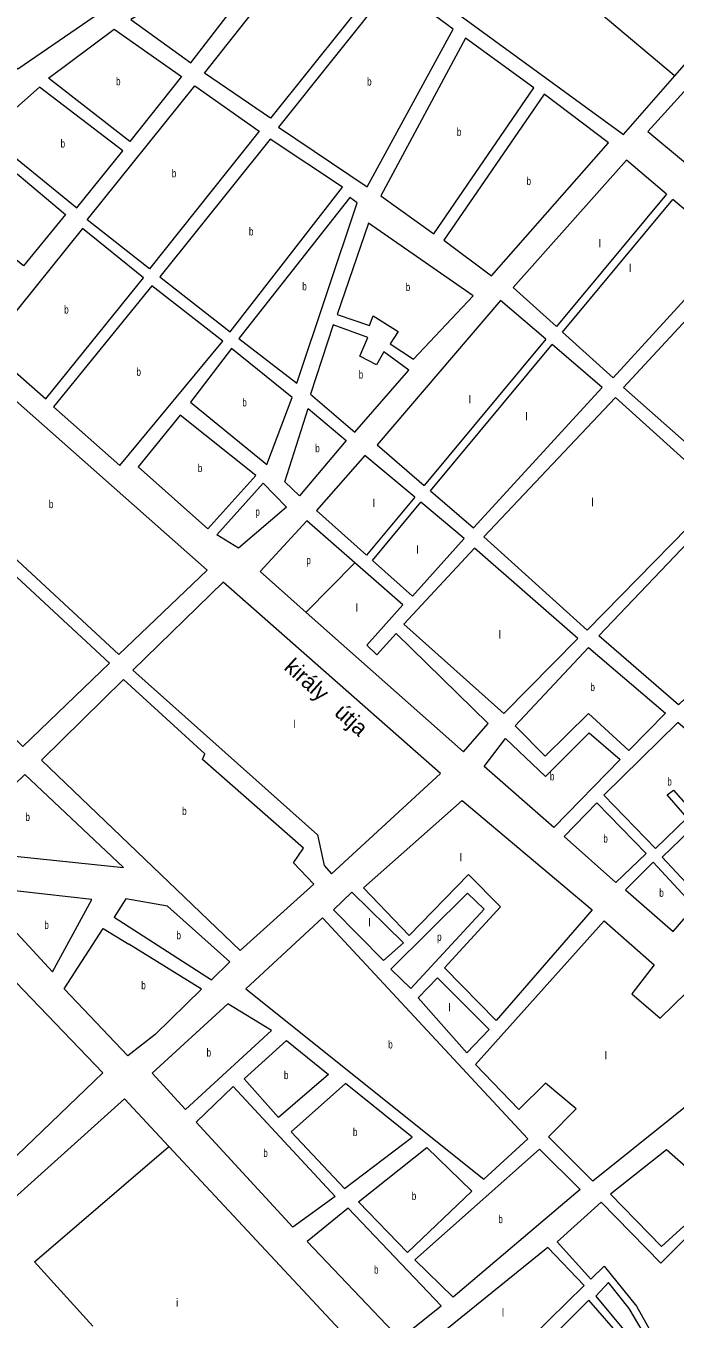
# Model space of a CAD drawing. Extents: x 639657 to 671642, y 222838 to 252123.
# Drawn here: x 655224 to 656035, y 240268 to 241884 of the extents above; entities that cross this region are included whole.
import ezdxf
from ezdxf.enums import TextEntityAlignment as Align

# ---------------------------------------------------------------- set-up
doc = ezdxf.new("R2010")
doc.units = 0
doc.header["$LTSCALE"] = 4
doc.layers.add('1', color=7, linetype='Continuous', lineweight=13)
doc.layers.add('21', color=7, linetype='Continuous', lineweight=13)
doc.layers.add('22', color=7, linetype='Continuous')
doc.layers.add('7', color=7, linetype='Continuous')

msp = doc.modelspace()

# ---------------------------------------------------------------- linework, layer by layer
at = {"layer": '1'}
for p, q in [((656024.414, 241674.151), (655886.753, 241508.509)), ((655894.364, 241501.644), (656032.279, 241667.507)), ((655832.72, 241557.25), (655886.753, 241508.509)), ((655873.616, 241492.701), (655721.745, 241309.96)), ((655729.45, 241303.309), (655881.391, 241486.042)), ((655662.94, 241360.72), (655721.745, 241309.96)), ((655709.772, 241295.553), (655649.539, 241223.076)), ((655657.126, 241216.327), (655717.574, 241289.026)), ((655586.77, 241278.92), (655649.539, 241223.076)), ((655516.47, 241202.55), (655574.023, 241151.538)), ((655443.06, 240680.6), (655352.25, 240736.81)), ((655385.49, 240624.22), (655443.06, 240680.6))]:
    msp.add_line(p, q, dxfattribs=at)
for points in [[(655304.45, 242218.19), (655077.93, 241931.43), (655213.74, 241830.45), (655396.658, 241956.518)], [(655630.564, 242060.254), (655599.16, 242019.65), (655970.83, 241748.67), (656034.683, 241821.83), (656138.378, 241940.64), (656234.597, 242050.884)], [(656024.414, 241674.151), (655974.33, 241716.45), (655832.72, 241557.25)], [(655894.364, 241501.644), (655957.88, 241444.35), (656105.39, 241605.76), (656032.279, 241667.507)], [(655873.616, 241492.701), (655816.92, 241541.26), (655662.94, 241360.72)], [(655729.45, 241303.309), (655783.18, 241256.93), (655944.01, 241432.41), (655881.391, 241486.042)], [(655709.772, 241295.553), (655647.46, 241347.69), (655586.77, 241278.92)], [(655657.126, 241216.327), (655707.05, 241171.91), (655771.47, 241243.93), (655717.574, 241289.026)], [(655634.809, 241213.583), (655575.06, 241265.93), (655516.47, 241202.55)], [(655574.023, 241151.538), (655770.56, 240977.34), (655801.43, 241012.53), (655686.49, 241124.97), (655662.53, 241098.44), (655650.05, 241110.69), (655694.77, 241161.05), (655634.809, 241213.583)], [(655385.49, 240624.22), (655351.31, 240597.6), (655271.56, 240681.31), (655320.37, 240756.43), (655352.25, 240736.81)], [(655105.621, 240170.224), (655025.29, 240254.65), (655346.94, 240543.81), (655402.598, 240484.128), (655650.81, 240217.97)]]:
    msp.add_lwpolyline(points, dxfattribs=at)
for points in [[(655566.4, 242015.61), (655355.12, 241892.37), (655429.78, 241838.18)], [(655447.09, 241825.43), (655587.48, 242002.89), (655669.17, 241943.38), (655529.3, 241769.14)], [(655682.13, 241936.5), (655539.61, 241757.95), (655650.46, 241683.09), (655757.88, 241880.17)], [(655353.76, 241739.72), (655252.01, 241818.95), (655334.26, 241880.37), (655418.11, 241820.88)], [(655773.03, 241869.01), (655667.22, 241671.95), (655733.76, 241624.67), (655858.51, 241806.84)], [(656058.32, 241702.64), (656107.08, 241658.98), (656223.11, 241792.71), (656104.21, 241865.88), (656000.9, 241752.14), (656050.72, 241711.18), (656107.16, 241774), (656115.82, 241767.08)], [(655174.13, 241748.97), (655287.28, 241656.93), (655344.72, 241728.36), (655240.82, 241807.57)], [(655515.46, 241752.91), (655378.26, 241580.84), (655300.31, 241642), (655434.87, 241809.2)], [(655871.48, 241798.89), (655746.19, 241616.71), (655805.71, 241572.07), (655952.1, 241738.3)], [(655528.99, 241742.81), (655391.25, 241570.74), (655478.93, 241502.14), (655619.28, 241682.83)], [(655220.72, 241584.36), (655161.06, 241632.7), (655212.73, 241699.31), (655273.38, 241648.75)], [(655628.53, 241670.01), (655489.76, 241493.63), (655562.28, 241437.81), (655637.73, 241663.1)], [(655294.5, 241631.2), (655174.83, 241482.93), (655248.5, 241418.51), (655370.83, 241569.49)], [(655651.93, 241637.96), (655612.6, 241523.69), (655653.04, 241510.05), (655657.77, 241521.92), (655689.12, 241502.29), (655679.04, 241487.16), (655708.24, 241468.06), (655782.81, 241547.15)], [(655970.88, 241432.64), (656104.16, 241314.44), (656226.68, 241442.85), (656219.64, 241449.78), (656246.84, 241474.73), (656118.41, 241591.89)], [(655381.13, 241559.37), (655258.26, 241408.38), (655341.15, 241334.91), (655469.9, 241490.24)], [(655651.02, 241494.99), (655607.88, 241510.75), (655579.6, 241423.98), (655634.84, 241376.61), (655702.45, 241454.03), (655671.07, 241476.88), (655662.07, 241460.68), (655641.01, 241471.79)], [(655480.73, 241481.19), (655429.7, 241414.12), (655524.99, 241336.45), (655556.52, 241420.02)], [(655450.34, 241204.15), (655155.63, 241464.49), (655052.75, 241364.74), (655339.97, 241098.95)], [(655796.18, 241245.75), (655960.78, 241420.19), (656092.99, 241300.37), (655925.14, 241129.13)], [(655511.13, 241322.36), (655416.4, 241397.89), (655364.28, 241333.49), (655450.96, 241255.75)], [(655576.53, 241406.22), (655624.18, 241366.31), (655565.65, 241297.02), (655547.22, 241314.6)], [(654947.24, 241256.9), (655220.01, 240984), (655328.24, 241088.11), (655043.72, 241351.76)], [(655462.56, 241248.47), (655520.36, 241312.76), (655549.64, 241282.91), (655489.42, 241231.91)], [(655939.71, 241122.26), (656103.26, 241293.47), (656209.99, 241198.16), (656039.37, 241036.03)], [(655784.48, 241231.68), (655696.06, 241136.88), (655821.21, 241025.06), (655913.4, 241118.82)], [(655470.36, 241189.27), (655357.34, 241079.21), (655588.14, 240873.69), (655596.54, 240835.06), (655605.77, 240824.93), (655741.76, 240950.22)], [(655927.12, 241025.28), (655872.76, 240972.04), (655835.16, 241009.89), (655926.75, 241107.53), (656023.34, 241025.68), (655977.51, 240979.08)], [(655491.56, 240728.84), (655583.84, 240811.85), (655558.34, 240838.51), (655570.55, 240856.88), (655444.33, 240967.61), (655447.49, 240974.63), (655345.62, 241067.83), (655243.28, 240967)], [(656057.73, 240901.66), (656109.99, 240952.24), (656038.49, 241013.99), (655946.28, 240922.92), (656010.83, 240856.28), (656050.43, 240894.6), (656025.3, 240923.58), (656033.31, 240929.56)], [(655883.73, 240882.62), (655796.52, 240958.75), (655823.37, 240993.74), (655873.13, 240946.31), (655927.68, 241000.81), (655966.56, 240967.5)], [(655222.47, 240949.09), (655125.97, 240855.84), (655345.7, 240832.85)], [(656121.35, 240944.27), (656018.99, 240845.6), (656072.71, 240788), (656181.48, 240891.03)], [(655931.39, 240779.83), (655811.64, 240641.77), (655747.1, 240707.34), (655816.97, 240783.79), (655776.8, 240823.79), (655702.66, 240747.81), (655645.7, 240807.53), (655768.93, 240916.59)], [(655896.73, 240871.44), (655961.2, 240813.94), (655999.06, 240850.27), (655937.22, 240913.71)], [(655973.11, 240804.9), (656032.69, 240752.73), (656059.31, 240783.59), (656007.75, 240839.59)], [(655082.17, 240823.76), (655319.78, 240576.37), (655201.42, 240462.51), (654953.95, 240731.31)], [(655157.81, 240809.36), (655257.08, 240702.5), (655306.22, 240792.81)], [(655695.75, 240738.62), (655631.23, 240802.03), (655608.31, 240779.8), (655670.68, 240716.37)], [(655704.85, 240681.72), (655679.91, 240705.7), (655775.85, 240800.56), (655796.45, 240780.85)], [(655478.78, 240714.76), (655400.76, 240784.51), (655348.53, 240793.75), (655334.22, 240770.52), (655455.85, 240692.53)], [(655498.68, 240681.084), (655796.16, 240443.32), (655851.09, 240493.76), (655594.42, 240770.01)], [(656133.99, 240602.55), (655932.19, 240440.7), (655876.87, 240496.13), (655911.51, 240531.35), (655873.06, 240563.28), (655839.99, 240530.53), (655785.88, 240586.59), (655946.57, 240765.98), (656008.86, 240711.15), (655981.23, 240674.9), (656016.43, 240644.56), (656049.48, 240676.55)], [(655713.91, 240669.7), (655738.06, 240694.9), (655802.6, 240630.41), (655774.76, 240600.97)], [(655476, 240662.6), (655381.61, 240575.81), (655423.39, 240530.48), (655530.59, 240629.2)], [(655602.03, 240573.9), (655539.6, 240520.17), (655496.71, 240568.72), (655549.52, 240616.46)], [(655482.82, 240558.93), (655610.34, 240421.87), (655557.45, 240383.27), (655436.43, 240514.47)], [(655555.34, 240502.57), (655622.08, 240431.64), (655706.46, 240495.77), (655623.09, 240562.79)], [(655781.24, 240428.14), (655700.73, 240351.69), (655639.43, 240415.13), (655724.85, 240483.03)], [(655916.69, 240430.35), (655757.66, 240295.73), (655709.94, 240342.63), (655865.72, 240480.99)], [(656038.26, 240112.12), (656167.07, 240135.24), (656138.48, 240333.32), (656161.37, 240359.31), (656024.31, 240480.17), (655954.37, 240424.76), (656018.37, 240359.19), (656046.1, 240384.68), (656055.85, 240376.7), (656017.48, 240338.22), (655942.63, 240414.45), (655887.738, 240364.976), (655929.677, 240318.542), (655946.632, 240334.615), (655986.76, 240284.75), (656010.24, 240243.03)], [(655575.48, 240365.5), (655690.95, 240243.68), (655742.7, 240284.86), (655626.6, 240406.96)], [(655875.92, 240357.99), (655708.83, 240222.76), (655766.91, 240158.75), (655921.49, 240310.54)], [(656004.633, 240105.124), (656030.511, 240109.589), (656001.956, 240240.854), (655977.863, 240281.93), (655951.986, 240314.077), (655935.924, 240297.111), (655976.971, 240247.998)], [(655778.86, 240144.88), (655804.2, 240074.15), (655996.42, 240101.56), (655969.38, 240243.76), (655927.56, 240292.32)]]:
    msp.add_lwpolyline(points, close=True, dxfattribs=at)
at = {"layer": '21'}
for points in [[(656034.683, 241821.83), (656034.183, 241822.251), (655900.924, 241934.491), (656002.51, 242059.608), (656137.878, 241941.078), (656138.378, 241940.64)], [(655574.023, 241151.538), (655574.513, 241152.038), (655634.319, 241213.083), (655634.809, 241213.583)], [(655307.254, 240259.646), (655234.53, 240339.969), (655402.098, 240483.699), (655402.598, 240484.128)]]:
    msp.add_lwpolyline(points, dxfattribs=at)

# ---------------------------------------------------------------- texts
at = {"layer": '22'}
msp.add_text('király   útja', height=20, rotation=317.863, dxfattribs=at).set_placement((655592.627, 241038.258), align=Align.CENTER)
at = {"layer": '7', "width": 0.75}
for s, p in [('b', (655336.483, 241810.045)), ('b', (655650.257, 241809.795)), ('b', (655762.427, 241746.84)), ('b', (655267.151, 241732.25)), ('b', (655406.141, 241695.02)), ('b', (655849.535, 241685.48)), ('b', (655502.531, 241622.475)), ('b', (655569.174, 241553.91)), ('b', (655698.528, 241553.01)), ('b', (655271.666, 241524.855)), ('b', (655361.988, 241447.14)), ('b', (655639.716, 241443.68)), ('b', (655494.248, 241408.82)), ('b', (655585.417, 241351.62)), ('b', (655438.627, 241326.82)), ('b', (655252.496, 241281.72)), ('p', (655510.585, 241272.335)), ('p', (655574.331, 241211.764)), ('b', (655929.367, 241053.191)), ('b', (655878.716, 240941.715)), ('b', (656025.482, 240935.135)), ('b', (655223.205, 240890.97)), ('b', (655419.079, 240898.335)), ('b', (655945.557, 240863.825)), ('b', (656015.414, 240796.16)), ('b', (655246.799, 240755.93)), ('b', (655411.978, 240743.14)), ('p', (655737.755, 240741.14)), ('b', (655367.99, 240680.587)), ('b', (655449.64, 240596.54)), ('b', (655676.65, 240606.665)), ('b', (655546.304, 240568.315)), ('b', (655632.521, 240497.215)), ('b', (655520.486, 240471.1)), ('b', (655706.061, 240417.36)), ('b', (655814.257, 240388.36)), ('b', (655658.897, 240325.32))]:
    msp.add_text(s, height=10, dxfattribs=at).set_placement(p)
at = {"layer": '7'}
for s, p in [('l', (655939.536, 241607.551)), ('l', (655977.491, 241576.83)), ('l', (655777.11, 241412.614)), ('l', (655847.997, 241391.388)), ('l', (655657.105, 241283.028)), ('l', (655930.605, 241284.145)), ('l', (655711.805, 241224.937)), ('l', (655635.894, 241152.325)), ('l', (655814.507, 241118.811)), ('l', (655557.751, 241007.1)), ('l', (655765.906, 240840.46)), ('l', (655651.688, 240759.2)), ('l', (655751.629, 240652.938)), ('l', (655947.049, 240593.109)), ('i', (655411.306, 240284.165)), ('l', (655818.553, 240271.643))]:
    msp.add_text(s, height=10, dxfattribs=at).set_placement(p)

doc.saveas('drawing.dxf')
